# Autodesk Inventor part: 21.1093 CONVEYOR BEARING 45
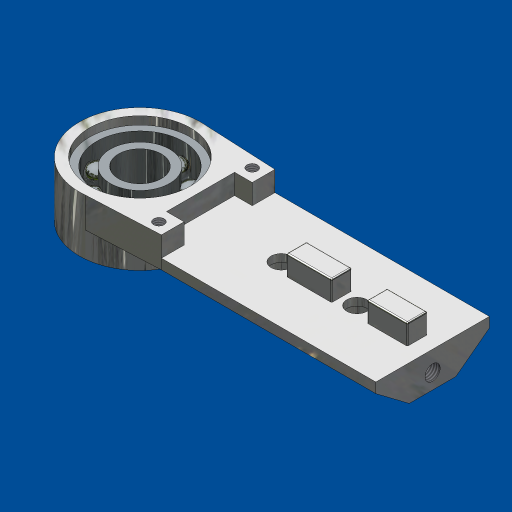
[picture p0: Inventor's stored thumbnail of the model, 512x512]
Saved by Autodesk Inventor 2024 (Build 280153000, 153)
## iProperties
Created: 2007-04
Part Number: 21.1093 CONVEYOR BEARING 45
Document SubType Name: Modeling
Designer: Andy Moles
Material: Aluminum-6061
Mass: 199.951 g
Surface Area: 277.121 cm^2
Volume: 73.7826 cm^3
Density: 2.71 g/cm^3
Appearance: Anodized - White
Author: Andy Moles
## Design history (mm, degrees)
feature "Base1"
hole "Hole1" diameter "d2" = 6; stored, may be unused: countersink angle "d6" = 90 deg, drill point angle "d8" = 0 deg; dims "d0" = 10, "d1" = 10, "d3" = 6, "d4" = 4, "d5" = 2, "d7" = 28
thread "Thread1" dims "d9" = 10, "d10" = 0
sketch "Sketch1"
  geometry: C1 r 24 at (-22.154, 9.23); A1 r 24 centre (-22.154, 9.23) between (0, 18.459) and (0, 0) reference; 1 further point
  constraints: 1 centre point, 1 coincident, 1 concentric
extrude "Extrusion1" join sketch "Sketch1" distance "d11" = 2.8; taper "d12" = 0 deg
sketch "Sketch2"
  geometry: L1 (31, 22.5)-(31, -22.5) reference; L2 (24, -13.5)-(51.382, -13.5); L3 (51.382, -13.5)-(51.382, 13.5); L4 (51.382, 13.5)-(24, 13.5); L5 (24, 13.5)-(24, -13.5); C1 r 20.001 at (0, 0) reference; 2 further points
  constraints: 8 end point, 2 parallel, 1 horizontal, 1 horizontal alignment, 1 midpoint, 1 perpendicular
  dimensions: "d13" = 27 distance of L2.end L3.end; "d14" = 7 distance between parallel lines of L5 L1
extrude "Extrusion2" cut sketch "Sketch2" stored distance "d15" = 10; taper "d16" = 0 deg
sketch "Sketch3"
  geometry: L1 (31, 22.5)-(31, 13.5) reference; L2 (31, -13.5)-(31, -22.5) reference; L3 (116, 22.5)-(31, 22.5) reference; L4 (116, -22.5)-(31, -22.5) reference; 3 further points
  dimensions: "d24" = 5 distance from line of point (26, -18.5) L2; "d25" = 5 distance from line of point (26, 18.5) L1; "d26" = 4 distance from line of point (26, 18.5) L3; "d27" = 4 distance from line of point (26, -18.5) L4
hole "Hole2" sketch "Sketch3" at (26, -18.5), (26, 18.5) diameter "d17" = 4.134; stored, may be unused: countersink angle "d21" = 90 deg, drill point angle "d23" = 118 deg; dims "d18" = 6, "d19" = 4, "d20" = 2, "d22" = 7
sketch "Sketch4"
  geometry: L1 (0, 0)-(18, 0) reference; L2 (18, 8)-(18, 0) reference; L3 (0, 8)-(18, 8) reference; L4 (0, 0)-(0, 8) reference; 1 further point
extrude "Extrusion3" join sketch "Sketch4" distance "d28" = 5; taper "d29" = 0 deg
sketch "Sketch5"
  geometry: L1 (49, 26.5)-(49, 18.5) reference; L2 (63, 26.5)-(79, 26.5); L3 (79, 26.5)-(79, 18.5); L4 (79, 18.5)-(63, 18.5); L5 (63, 18.5)-(63, 26.5); L6 (49, 26.5)-(31, 26.5) reference; L7 (31, 18.5)-(49, 18.5) reference; 1 further point
  constraints: 8 end point, 2 collinear, 2 parallel, 1 horizontal, 1 perpendicular
  dimensions: "d30" = 16 distance of L2.start L2.end; "d31" = 14 distance between parallel lines of L5 L1
extrude "Extrusion4" join sketch "Sketch5" distance "d32" = 8; taper "d33" = 0 deg
fillet "Fillet1" dims "d34" = 0.5
body "Solid1"
